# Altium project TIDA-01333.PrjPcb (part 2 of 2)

## Sheet TIDA-01333_Power_Stage.SchDoc: Power Stage
size 431 x 279 mm; Date: Not shown in title block; ApprovedBy: Not shown in title block; CheckedBy: Not shown in title block; Author: Not shown in title block; CompanyName: Not shown in title block; DrawnBy: Tobias Puetz; Engineer: Not shown in title block; Organization: Not shown in title block; Address1: Not shown in title block; Address2: Not shown in title block; Address3: Not shown in title block; Address4: Not shown in title block; DocumentNumber: 4; Revision: Use project parameter SCH_Rev; SheetNumber: 4; SheetTotal: 10; PageSetup: Record=PageOptions¦CenterHorizontal=True¦CenterVertical=True¦PrintScale=0.66¦XCorrection=1.00¦YCorrection=1.00¦PrintKind=0¦BorderSize=5000000¦LeftOffset=0¦BottomOffset=0¦Orientation=2¦PaperLength=1000¦PaperWidth=1000¦Scale=100¦PaperSource=15¦PrintQuality=600¦MediaType=1¦DitherType=10¦PrintScaleMode=1¦PaperKind=Letter
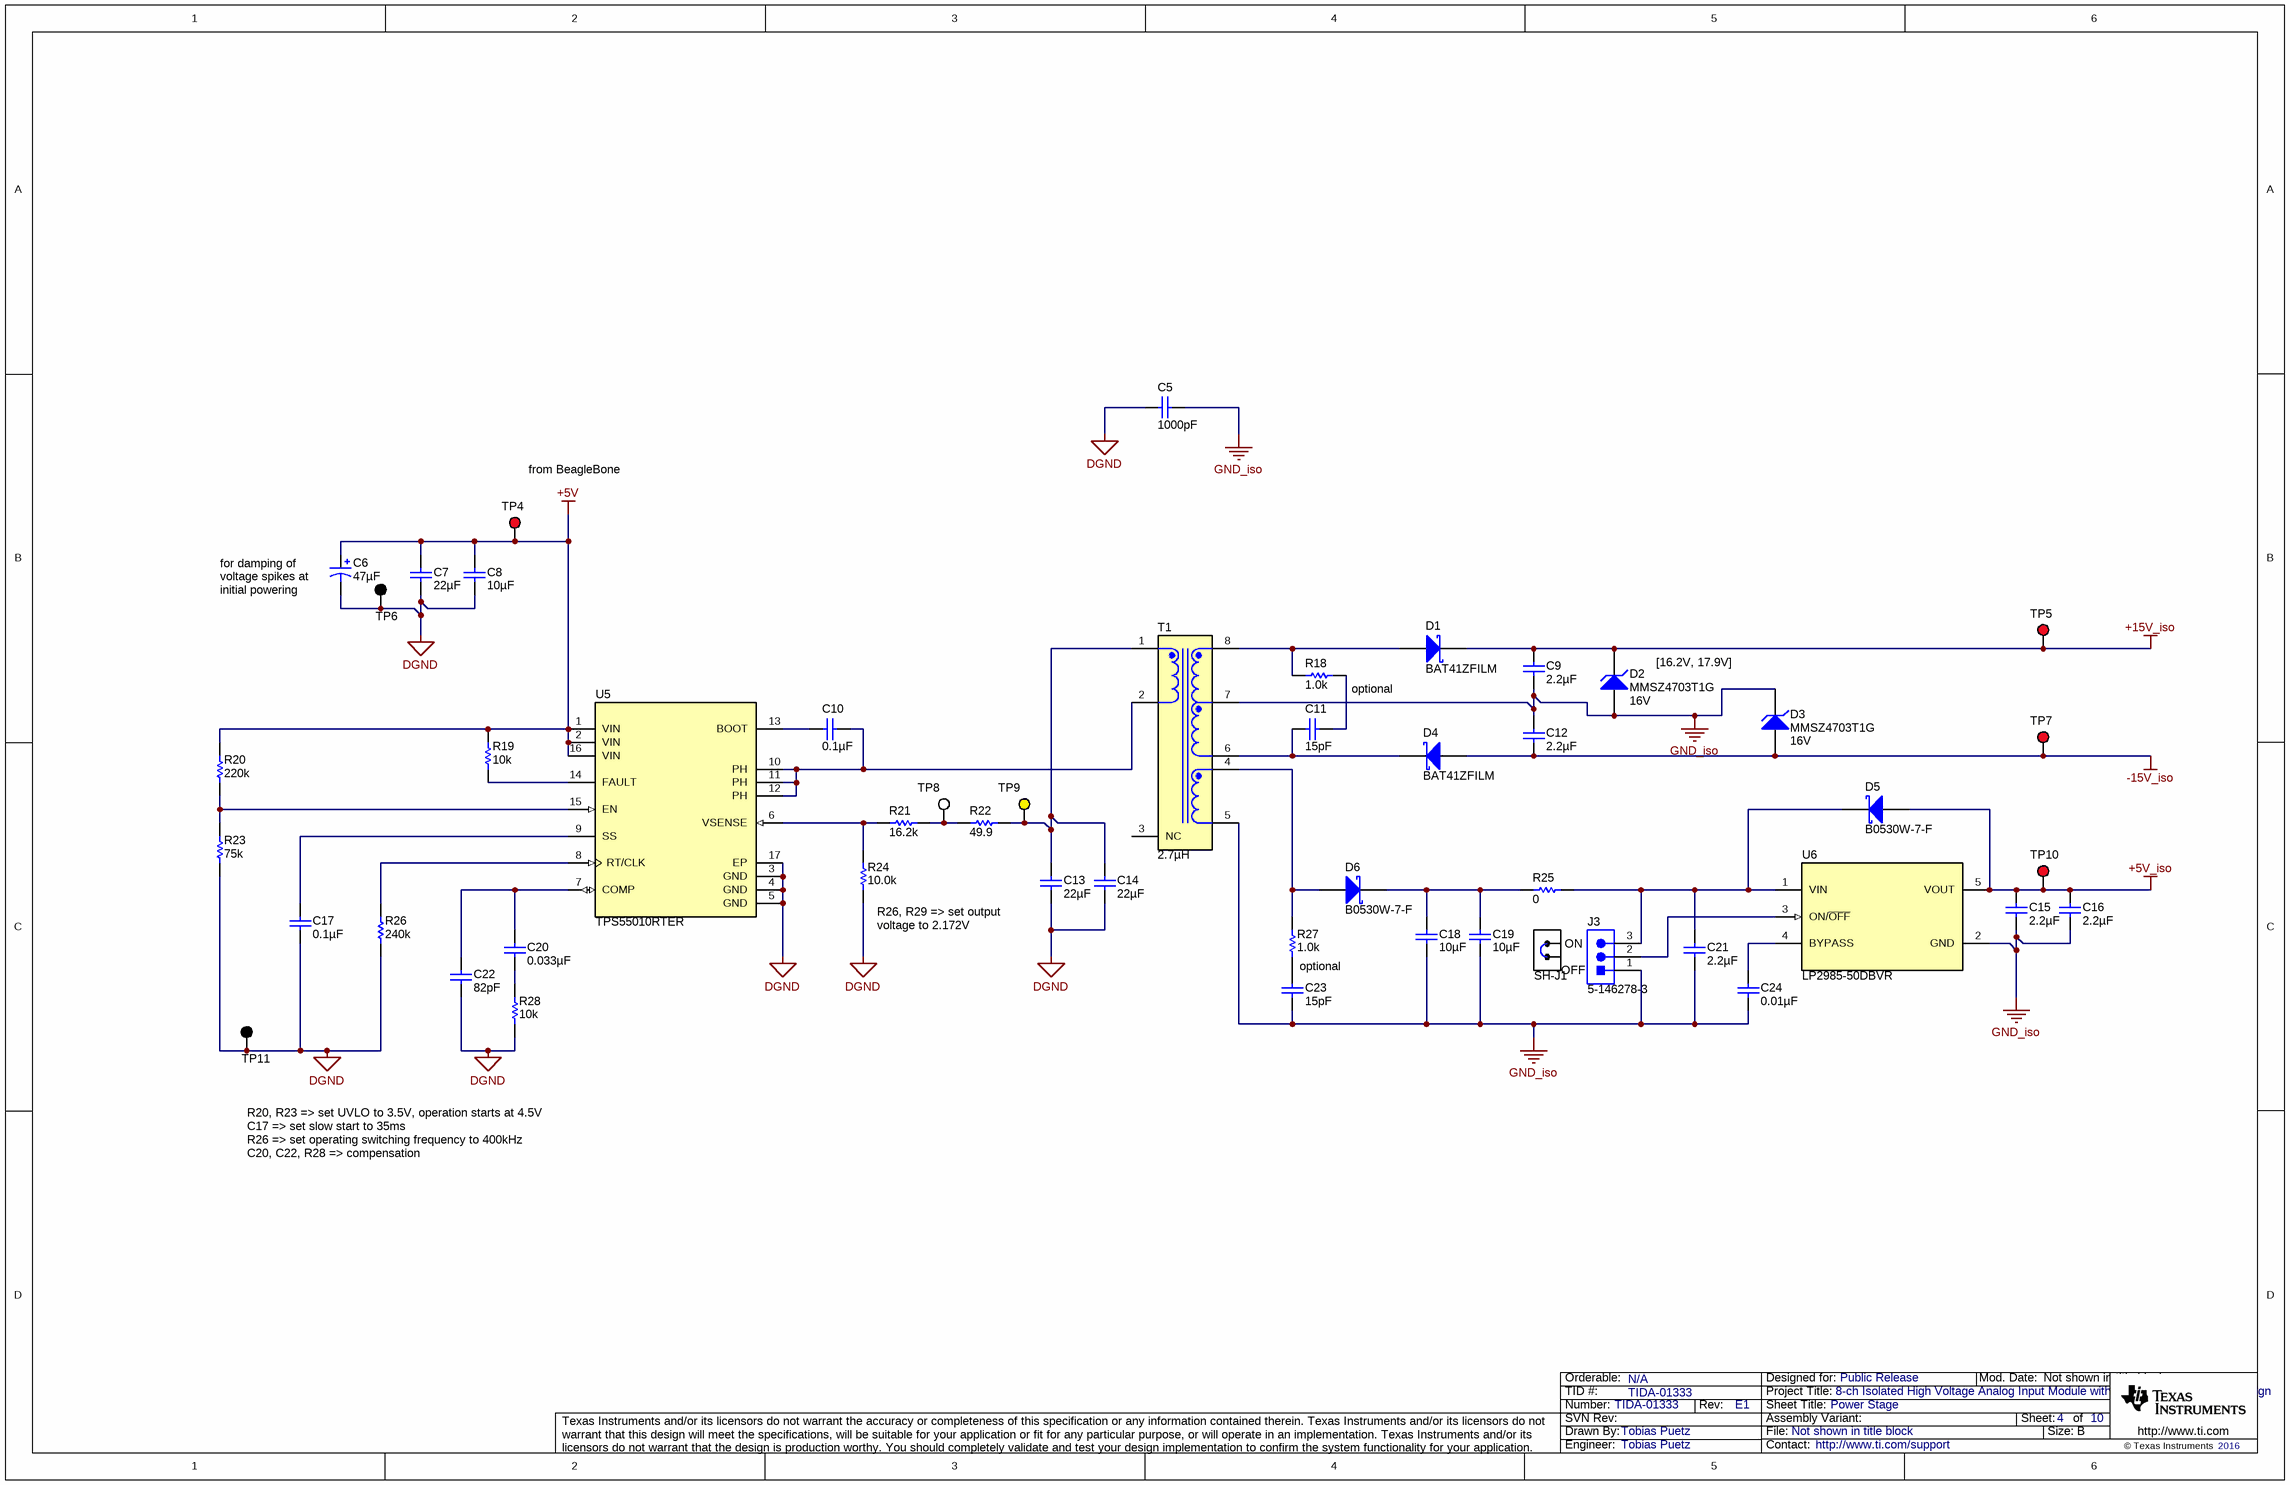
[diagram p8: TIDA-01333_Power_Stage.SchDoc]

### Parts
C5  ValueDisplayed: 1000pF  [1206_190]  (hidden comment: 202R18W102KV4E)
C6  ValueDisplayed: 47µF  [CAPPRD200W50D500H1100]  (hidden comment: ECA-1VM470)
C7  ValueDisplayed: 22µF  [1206_180]  (hidden comment: GRM31CR71A226KE15L)
C8  ValueDisplayed: 10µF  [0805_HV]  (hidden comment: C2012X7R1A106K125AC)
C9  ValueDisplayed: 2.2µF  [1206_180]  (hidden comment: GRM31CR71H225KA88L)
C10  ValueDisplayed: 0.1µF  [0603]  (hidden comment: GRM188R71H104KA93D)
C11  ValueDisplayed: 15pF  [0603]  (hidden comment: GRM1885C1H150JA01D)
C12  ValueDisplayed: 2.2µF  [1206_180]  (hidden comment: GRM31CR71H225KA88L)
C13  ValueDisplayed: 22µF  [1206_180]  (hidden comment: GRM31CR71A226KE15L)
C14  ValueDisplayed: 22µF  [1206_180]  (hidden comment: GRM31CR71A226KE15L)
C15  ValueDisplayed: 2.2µF  [0603]  (hidden comment: GRM188R71A225KE15D)
C16  ValueDisplayed: 2.2µF  [0603]  (hidden comment: GRM188R71A225KE15D)
C17  ValueDisplayed: 0.1µF  [0603]  (hidden comment: GRM188R71H104KA93D)
C18  ValueDisplayed: 10µF  [0805_HV]  (hidden comment: C2012X7R1A106K125AC)
C19  ValueDisplayed: 10µF  [0805_HV]  (hidden comment: C2012X7R1A106K125AC)
C20  ValueDisplayed: 0.033µF  [0603]  (hidden comment: GRM188R71H333KA61D)
C21  ValueDisplayed: 2.2µF  [0603]  (hidden comment: GRM188R71A225KE15D)
C22  ValueDisplayed: 82pF  [0603]  (hidden comment: GRM1885C1H820JA01D)
C23  ValueDisplayed: 15pF  [0603]  (hidden comment: GRM1885C1H150JA01D)
C24  ValueDisplayed: 0.01µF  [0603]  (hidden comment: 06031C103KAT2A)
D1  BAT41ZFILM  [SOD-123]
D2  MMSZ4703T1G  value 16V  [SOD-123]
D3  MMSZ4703T1G  value 16V  [SOD-123]
D4  BAT41ZFILM  [SOD-123]
D5  B0530W-7-F  [SOD-123]
D6  B0530W-7-F  [SOD-123]
J3  5-146278-3  [TE_5-146278-3]
R18  ValueDisplayed: 1.0k  [0805_HV]  (hidden comment: ERJ-6GEYJ102V)
R19  ValueDisplayed: 10k  [0603]  (hidden comment: CRCW060310K0JNEA)
R20  ValueDisplayed: 220k  [0603]  (hidden comment: CRCW0603220KJNEA)
R21  ValueDisplayed: 16.2k  [0603]  (hidden comment: CRCW060316K2FKEA)
R22  ValueDisplayed: 49.9  [0603]  (hidden comment: CRCW060349R9FKEA)
R23  ValueDisplayed: 75k  [0603]  (hidden comment: CRCW060375K0JNEA)
R24  ValueDisplayed: 10.0k  [0603]  (hidden comment: CRCW060310K0FKEA)
R25  ValueDisplayed: 0  [0603]  (hidden comment: CRCW06030000Z0EA)
R26  ValueDisplayed: 240k  [0603]  (hidden comment: CRCW0603240KJNEA)
R27  ValueDisplayed: 1.0k  [0805_HV]  (hidden comment: ERJ-6GEYJ102V)
R28  ValueDisplayed: 10k  [0603]  (hidden comment: CRCW060310K0JNEA)
SH-J1  60900213421  [Wurth_60900213421]  (value not drawn)
T1  ValueDisplayed: 2.7µH  [Wurth_750316170]  (hidden comment: 750316449)
TP4  5000  [Keystone5000]  (value not drawn)
TP5  5000  [Keystone5000]  (value not drawn)
TP6  5001  [Keystone5001]  (value not drawn)
TP7  5000  [Keystone5000]  (value not drawn)
TP8  5002  [Keystone5002]  (value not drawn)
TP9  5004  [Keystone5004]  (value not drawn)
TP10  5000  [Keystone5000]  (value not drawn)
TP11  5001  [Keystone5001]  (value not drawn)
U5  TPS55010RTER  [RTE0016F]
U6  LP2985-50DBVR  [DBV0005A_N]

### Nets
+5V: C6.1(+) C7.1 C8.2 R19.2 R20.2 TP4.1 U5.1(VIN) U5.2(VIN) U5.16(VIN)
+5V_iso: C15.1 C16.1 D5.2(A) TP10.1 U6.5(VOUT)
+15V_iso: C9.1 D1.1(K) D2.1(K) TP5.1
-15V_iso: C12.2 D3.2(A) D4.2(A) TP7.1
DGND: C5.2 C6.2(-) C7.2 C8.1 C13.2 C14.2 C17.2 C22.1 R23.1 R24.1 R26.1 R28.1 TP6.1 TP11.1 U5.3(GND) U5.4(GND) U5.5(GND) U5.17(EP)
GND_iso: C5.1 C9.2 C12.1 C15.2 C16.2 C18.2 C19.1 C21.2 C23.2 C24.2 D2.2(A) D3.1(K) J3.1 T1.5 T1.7 U6.2(GND)
NetC10_1: C10.1 T1.2 U5.10(PH) U5.11(PH) U5.12(PH)
NetC10_2: C10.2 U5.13(BOOT)
NetC11_1: C11.1 R18.1
NetC11_2: C11.2 D4.1(K) T1.6
NetC13_1: C13.1 C14.1 R22.2 T1.1 TP9.1
NetC17_1: C17.1 U5.9(SS)
NetC18_1: C18.1 C19.2 D6.1(K) R25.1
NetC20_1: C20.1 C22.2 U5.7(COMP)
NetC20_2: C20.2 R28.2
NetC21_1: C21.1 D5.1(K) J3.3 R25.2 U6.1(VIN)
NetC23_1: C23.1 R27.1
NetC24_1: C24.1 U6.4(BYPASS)
NetD1_2: D1.2(A) R18.2 T1.8
NetD6_2: D6.2(A) R27.2 T1.4
NetJ3_2: J3.2 U6.3(ON/~{OFF})
NetR19_1: R19.1 U5.14(FAULT)
NetR20_1: R20.1 R23.2 U5.15(EN)
NetR21_1: R21.1 R22.1 TP8.1
NetR21_2: R21.2 R24.2 U5.6(VSENSE)
NetR26_2: R26.2 U5.8(RT/CLK)

Not connected (* = marked no-connect by the designer): T1 3(NC)

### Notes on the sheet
- from BeagleBone
- (near C6) for damping of voltage spikes at initial powering
- (near R18) optional
- [16.2V, 17.9V]
- (near R24) R26, R29 => set output voltage to 2.172V
- (near R27) optional
- ON
- OFF
- R20, R23 => set UVLO to 3.5V, operation starts at 4.5V
  C17 => set slow start to 35ms
  R26 => set operating switching frequency to 400kHz
  C20, C22, R28 => compensation

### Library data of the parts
C5 = 202R18W102KV4E: CAP, CERM, 1000 pF, 2000 V, +/- 10%, X7R, 1206_190; Manufacturer: Johanson Technology; Polarized: N; CompType: Capacitor; Value: 1000pF; U/M: EA; Cap_F: 0.000000001; Tolerance_%: 10; Value1: Unknown; VDC_V: 2000; Value2: 2000V; TaMin_C: -55; TaMax_C: 125; Cap_Case: 1206; AEC Category: Q200; SizeArea_mm2: 5.12; SizeAreaWB_mm2: 10.92; SizeX_mm: 3.2; SizeY_mm: 1.6; SizeZ_mm: 1.9
C6 = ECA-1VM470: CAP, AL, 47 µF, 35 V, +/- 20%, TH; Manufacturer: Panasonic; Polarized: Y; CompType: Capacitor; Value: 47uF; U/M: EA; Cap_F: 0.000047; Tolerance_%: 20; Value1: Unknown; VDC_V: 35; Value2: 35V; IRMS_A: 0.13; TaMin_C: -40; TaMax_C: 85; Cap_Case: RCAP, 5x11mm; AEC Category: Q200; AEC Qualified: N
C7 C13 C14 = GRM31CR71A226KE15L: CAP, CERM, 22 µF, 10 V, +/- 10%, X7R, 1206; Manufacturer: MuRata; Polarized: N; CompType: Capacitor; Value: 22uF; U/M: EA; Cap_F: 0.000022; Tolerance_%: 10; Value1: Unknown; Value2: 10V; TaMin_C: -55; TaMax_C: 125; Cap_Case: 1206; AEC Category: Q200; SizeArea_mm2: 5.12; SizeAreaWB_mm2: 10.92; SizeX_mm: 3.2; SizeY_mm: 1.6; SizeZ_mm: 1.8
C8 C18 C19 = C2012X7R1A106K125AC: CAP, CERM, 10 µF, 10 V, +/- 10%, X7R, 0805; Manufacturer: TDK; Polarized: N; CompType: Capacitor; Value: 10uF; U/M: EA; Cap_F: 0.00001; Tolerance_%: 10; ESR_ohm: 0.001063; Value1: 0.001063 ohm; Value2: 10V; IRMS_A: 6.32908; TaMin_C: -55; TaMax_C: 125; Cap_Case: 0805; AEC Category: Q200; SizeArea_mm2: 2.5; SizeAreaWB_mm2: 6.75; SizeX_mm: 2; SizeY_mm: 1.25; SizeZ_mm: 1.45
C9 C12 = GRM31CR71H225KA88L: CAP, CERM, 2.2 µF, 50 V, +/- 10%, X7R, 1206; Manufacturer: MuRata; Polarized: N; CompType: Capacitor; Value: 2.2uF; U/M: EA; Cap_F: 0.0000022; Tolerance_%: 10; Value1: Unknown; VDC_V: 50; Value2: 50V; TaMin_C: -55; TaMax_C: 125; Cap_Case: 1206; AEC Category: Q200; SizeArea_mm2: 5.12; SizeAreaWB_mm2: 10.92; SizeX_mm: 3.2; SizeY_mm: 1.6; SizeZ_mm: 1.8
C10 C17 = GRM188R71H104KA93D: CAP, CERM, 0.1 µF, 50 V, +/- 10%, X7R, 0603; Manufacturer: MuRata; Polarized: N; CompType: Capacitor; Value: 0.1uF; U/M: EA; Cap_F: 0.0000001; Tolerance_%: 10; Value1: Unknown; VDC_V: 50; Value2: 50V; TaMin_C: -55; TaMax_C: 125; SizeArea_mm2: 1.28; SizeAreaWB_mm2: 4.68; SizeX_mm: 1.6; SizeY_mm: 0.8; SizeZ_mm: 1; AEC Category: Q200
C11 C23 = GRM1885C1H150JA01D: CAP, CERM, 15 pF, 50 V, +/- 5%, C0G/NP0, 0603; Manufacturer: MuRata; Polarized: N; CompType: Capacitor; Value: 15pF; U/M: EA; Cap_F: 0.000000000015; Tolerance_%: 5; Value1: Unknown; VDC_V: 50; Value2: 50V; TaMin_C: -55; TaMax_C: 125; SizeArea_mm2: 1.28; SizeAreaWB_mm2: 4.68; SizeX_mm: 1.6; SizeY_mm: 0.8; SizeZ_mm: 1; AEC Category: Q200
C15 C16 C21 = GRM188R71A225KE15D: CAP, CERM, 2.2 µF, 10 V, +/- 10%, X7R, 0603; Manufacturer: MuRata; Polarized: N; CompType: Capacitor; Value: 2.2uF; U/M: EA; Cap_F: 0.0000022; Tolerance_%: 10; ESR_ohm: 0.009; Value1: 0.009 ohm; Value2: 10V; TaMin_C: -55; TaMax_C: 125; AEC Category: Q200; SizeArea_mm2: 1.28; SizeAreaWB_mm2: 4.68; SizeX_mm: 1.6; SizeY_mm: 0.8; SizeZ_mm: 1
C20 = GRM188R71H333KA61D: CAP, CERM, 0.033 µF, 50 V, +/- 10%, X7R, 0603; Manufacturer: MuRata; Polarized: N; CompType: Capacitor; Value: 0.033uF; U/M: EA; Cap_F: 0.000000033; Tolerance_%: 10; Value1: Unknown; VDC_V: 50; Value2: 50V; TaMin_C: -55; TaMax_C: 125; AEC Category: Q200; SizeArea_mm2: 1.28; SizeAreaWB_mm2: 4.68; SizeX_mm: 1.6; SizeY_mm: 0.8; SizeZ_mm: 1
C22 = GRM1885C1H820JA01D: CAP, CERM, 82 pF, 50 V, +/- 5%, C0G/NP0, 0603; Manufacturer: MuRata; Polarized: N; CompType: Capacitor; Value: 82pF; U/M: EA; Cap_F: 0.000000000082; Tolerance_%: 5; Value1: Unknown; VDC_V: 50; Value2: 50V; TaMin_C: -55; TaMax_C: 125; AEC Category: Q200; SizeArea_mm2: 1.28; SizeAreaWB_mm2: 4.68; SizeX_mm: 1.6; SizeY_mm: 0.8; SizeZ_mm: 1
C24 = 06031C103KAT2A: CAP, CERM, 0.01 µF, 100 V, +/- 10%, X7R, 0603; Manufacturer: AVX; Polarized: N; CompType: Capacitor; Value: 0.01uF; U/M: EA; Cap_F: 0.00000001; Tolerance_%: 10; ESR_ohm: 0.098; Value1: 0.098 ohm; VDC_V: 100; Value2: 100V; TaMin_C: -55; TaMax_C: 125; SizeArea_mm2: 1.28; SizeAreaWB_mm2: 4.68; SizeX_mm: 1.6; SizeY_mm: 0.8; SizeZ_mm: 1; AEC Category: Q200
D1 D4 = BAT41ZFILM: Diode, Schottky, 100 V, 0.2 A, SOD-123; Manufacturer: STMicroelectronics; U/M: EA; Vf_V: 1; Value: 100V; Value1: 0.2A; Value2: 1V; Io_A: 0.2; Vr_V: 100; TJmax_C: 150; SizeAreaWB_mm2: 13.095; SizeArea_mm2: 6.545; SizeX_mm: 3.85; SizeY_mm: 1.7; SizeZ_mm: 1.35; AEC Category: Q101
D2 D3 = MMSZ4703T1G: Diode, Zener, 16 V, 500 mW, SOD-123; Manufacturer: ON Semiconductor; SymbolCreator: a0412235; U/M: EA; Power_W: 0.5; Vz_V: 16; Value1: 0.5W; RJA_CperW: 340; AEC Category: Q101; SizeAreaWB_mm2: 13.095; SizeArea_mm2: 6.545; SizeX_mm: 3.85; SizeY_mm: 1.7; SizeZ_mm: 1.35
D5 D6 = B0530W-7-F: Diode, Schottky, 30 V, 0.5 A, SOD-123; Manufacturer: Diodes Inc.; U/M: EA; Vf_V: 0.43; Value: 30V; Value1: 0.5A; Value2: 0.43V; Io_A: 0.5; Vr_V: 30; TJmax_C: 125; AEC Category: Q101; SizeAreaWB_mm2: 13.095; SizeArea_mm2: 6.545; SizeX_mm: 3.85; SizeY_mm: 1.7; SizeZ_mm: 1.35
J3 = 5-146278-3: Header, 100mil, 3x1, Tin, TH; Manufacturer: TE Connectivity; SymbolCreator: a0799628
R18 R27 = ERJ-6GEYJ102V: RES, 1.0 k, 5%, 0.125 W, 0805; Manufacturer: Panasonic; CompType: Resistor; Value: 1.0k; Res_ohm: 1000; Value_Code: 1k00; Tolerance_%: 5; Power_W: 0.125; Value2: 0.125W; VDC_V: 150; TempCo: 200 ppm/C; EIA_Code: E24; U/M: EA; AEC Category: Q200; SizeArea_mm2: 2.5; SizeX_mm: 2; SizeY_mm: 1.25; SizeZ_mm: 1.45
R19 R28 = CRCW060310K0JNEA: RES, 10 k, 5%, 0.1 W, 0603; Manufacturer: Vishay-Dale; CompType: Resistor; Value: 10k; Res_ohm: 10000; Value_Code: 10k0; Tolerance_%: 5; Power_W: 0.1; Value2: 0.1W; VDC_V: 75; TempCo: 200 ppm/C; EIA_Code: E24; U/M: EA; AEC Category: Q200; SizeArea_mm2: 1.28; SizeX_mm: 1.6; SizeY_mm: 0.8; SizeZ_mm: 1
R20 = CRCW0603220KJNEA: RES, 220 k, 5%, 0.1 W, 0603; Manufacturer: Vishay-Dale; CompType: Resistor; Value: 220k; Res_ohm: 220000; Tolerance_%: 5; Power_W: 0.1; Value2: 0.1W; VDC_V: 75; TempCo: 200 ppm/C; EIA_Code: E24; U/M: EA; AEC Category: Q200; SizeArea_mm2: 1.28; SizeX_mm: 1.6; SizeY_mm: 0.8; SizeZ_mm: 1
R21 = CRCW060316K2FKEA: RES, 16.2 k, 1%, 0.1 W, 0603; Manufacturer: Vishay-Dale; CompType: Resistor; Value: 16.2k; Res_ohm: 16200; Value_Code: 16k2; Tolerance_%: 1; Power_W: 0.1; Value2: 0.1W; VDC_V: 75; TempCo: 100 ppm/C; EIA_Code: E96; U/M: EA; AEC Category: Q200; SizeArea_mm2: 1.28; SizeX_mm: 1.6; SizeY_mm: 0.8
R22 = CRCW060349R9FKEA: RES, 49.9, 1%, 0.1 W, 0603; Manufacturer: Vishay-Dale; CompType: Resistor; Value: 49.9; Value_Code: 49R9; Tolerance_%: 1; Power_W: 0.1; Value2: 0.1W; VDC_V: 75; TempCo: 100 ppm/C; SizeArea_mm2: 1.28; SizeX_mm: 1.6; SizeY_mm: 0.8; EIA_Code: E96; U/M: EA; AEC Category: Q200
R23 = CRCW060375K0JNEA: RES, 75 k, 5%, 0.1 W, 0603; Manufacturer: Vishay-Dale; CompType: Resistor; Value: 75k; Res_ohm: 75000; Value_Code: 75k0; Tolerance_%: 5; Power_W: 0.1; Value2: 0.1W; VDC_V: 75; TempCo: 200 ppm/C; SizeArea_mm2: 1.28; SizeX_mm: 1.6; SizeY_mm: 0.8; SizeZ_mm: 1; EIA_Code: E24; U/M: EA; AEC Category: Q200
R24 = CRCW060310K0FKEA: RES, 10.0 k, 1%, 0.1 W, 0603; Manufacturer: Vishay-Dale; CompType: Resistor; Value: 10.0k; Res_ohm: 10000; Value_Code: 10k0; Tolerance_%: 1; Power_W: 0.1; Value2: 0.1W; VDC_V: 75; TempCo: 100 ppm/C; EIA_Code: E96; U/M: EA; AEC Category: Q200; SizeArea_mm2: 1.28; SizeX_mm: 1.6; SizeY_mm: 0.8
R25 = CRCW06030000Z0EA: RES, 0, 5%, 0.1 W, 0603; Manufacturer: Vishay-Dale; CompType: Resistor; Value: 0; Value_Code: 0000; Tolerance_%: 5; Power_W: 0.1; Value2: 0.1W; VDC_V: 75; TempCo: 200 ppm/C; EIA_Code: E24; U/M: EA; AEC Category: Q200; SizeArea_mm2: 1.28; SizeX_mm: 1.6; SizeY_mm: 0.8; SizeZ_mm: 1
R26 = CRCW0603240KJNEA: RES, 240 k, 5%, 0.1 W, 0603; Manufacturer: Vishay-Dale; CompType: Resistor; Value: 240k; Res_ohm: 240000; Tolerance_%: 5; Power_W: 0.1; Value2: 0.1W; VDC_V: 75; TempCo: 200 ppm/C; EIA_Code: E24; U/M: EA; AEC Category: Q200; SizeArea_mm2: 1.28; SizeX_mm: 1.6; SizeY_mm: 0.8; SizeZ_mm: 1
SH-J1 = 60900213421: Shunt, 2.54mm, Gold, Black; Manufacturer: Wurth Elektronik
T1 = 750316449: Transformer, 2.7 uH, SMT; Manufacturer: Wurth Elektronik; SymbolCreator: Altium; Value: 2.7uH; Lp: 2.7; DCR_ohm: 0.015; LeakageL: 0.5; Ns1toNp: 7; Ns3toNp: 3; Rs1: 1.45; Rs3: 0.435
TP4 TP5 TP7 TP10 = 5000: Test Point, Miniature, Red, TH; Manufacturer: Keystone; CompType: Test Point Loop; ContactFinish: Silver
TP6 TP11 = 5001: Test Point, Miniature, Black, TH; Manufacturer: Keystone; CompType: Test Point Loop; ContactFinish: Silver
TP8 = 5002: Test Point, Miniature, White, TH; Manufacturer: Keystone; CompType: Test Point Loop; ContactFinish: Silver
TP9 = 5004: Test Point, Miniature, Yellow, TH; Manufacturer: Keystone; CompType: Test Point Loop; ContactFinish: Silver
U5 = TPS55010RTER: 2.95V To 6V Input, 2W, Isolated DC/DC Converter with Integrated FETs, RTE0016F (WQFN-16); Manufacturer: Texas Instruments; SymbolCreator: Altium; SizeArea_mm2: 9; SizeAreaWB_mm2: 16; SizeX_mm: 3; SizeZ_mm: 0.8; CompType: IC; U/M: EA
U6 = LP2985-50DBVR: 150-mA Low-noise Low-dropout Regulator With Shutdown, DBV0005A; Alternate PartNumber: LP2985-50DBVT; Manufacturer: Texas Instruments; SymbolCreator: Altium; CompType: IC; U/M: EA; SizeArea_mm2: 8.12; SizeAreaWB_mm2: 14.82; SizeX_mm: 2.8; SizeY_mm: 2.9; SizeZ_mm: 1.45

## Sheet TIDA-01333_CoverSheet.SchDoc: Block Diagram
size 431 x 279 mm; Date: Not shown in title block; ApprovedBy: Not shown in title block; CheckedBy: Not shown in title block; Author: Not shown in title block; CompanyName: Not shown in title block; DrawnBy: Tobias Puetz; Engineer: Not shown in title block; Organization: Not shown in title block; Address1: Not shown in title block; Address2: Not shown in title block; Address3: Not shown in title block; Address4: Not shown in title block; DocumentNumber: 1; Revision: Use project parameter SCH_Rev; SheetNumber: 1; SheetTotal: 10; PageSetup: Record=PageOptions¦CenterHorizontal=True¦CenterVertical=True¦PrintScale=1.00¦XCorrection=1.00¦YCorrection=1.00¦PrintKind=0¦BorderSize=5000000¦LeftOffset=0¦BottomOffset=0¦Orientation=2¦PaperLength=1000¦PaperWidth=1000¦Scale=100¦PaperSource=15¦PrintQuality=600¦MediaType=1¦DitherType=10¦PaperKind=Letter¦PrintScaleMode=1
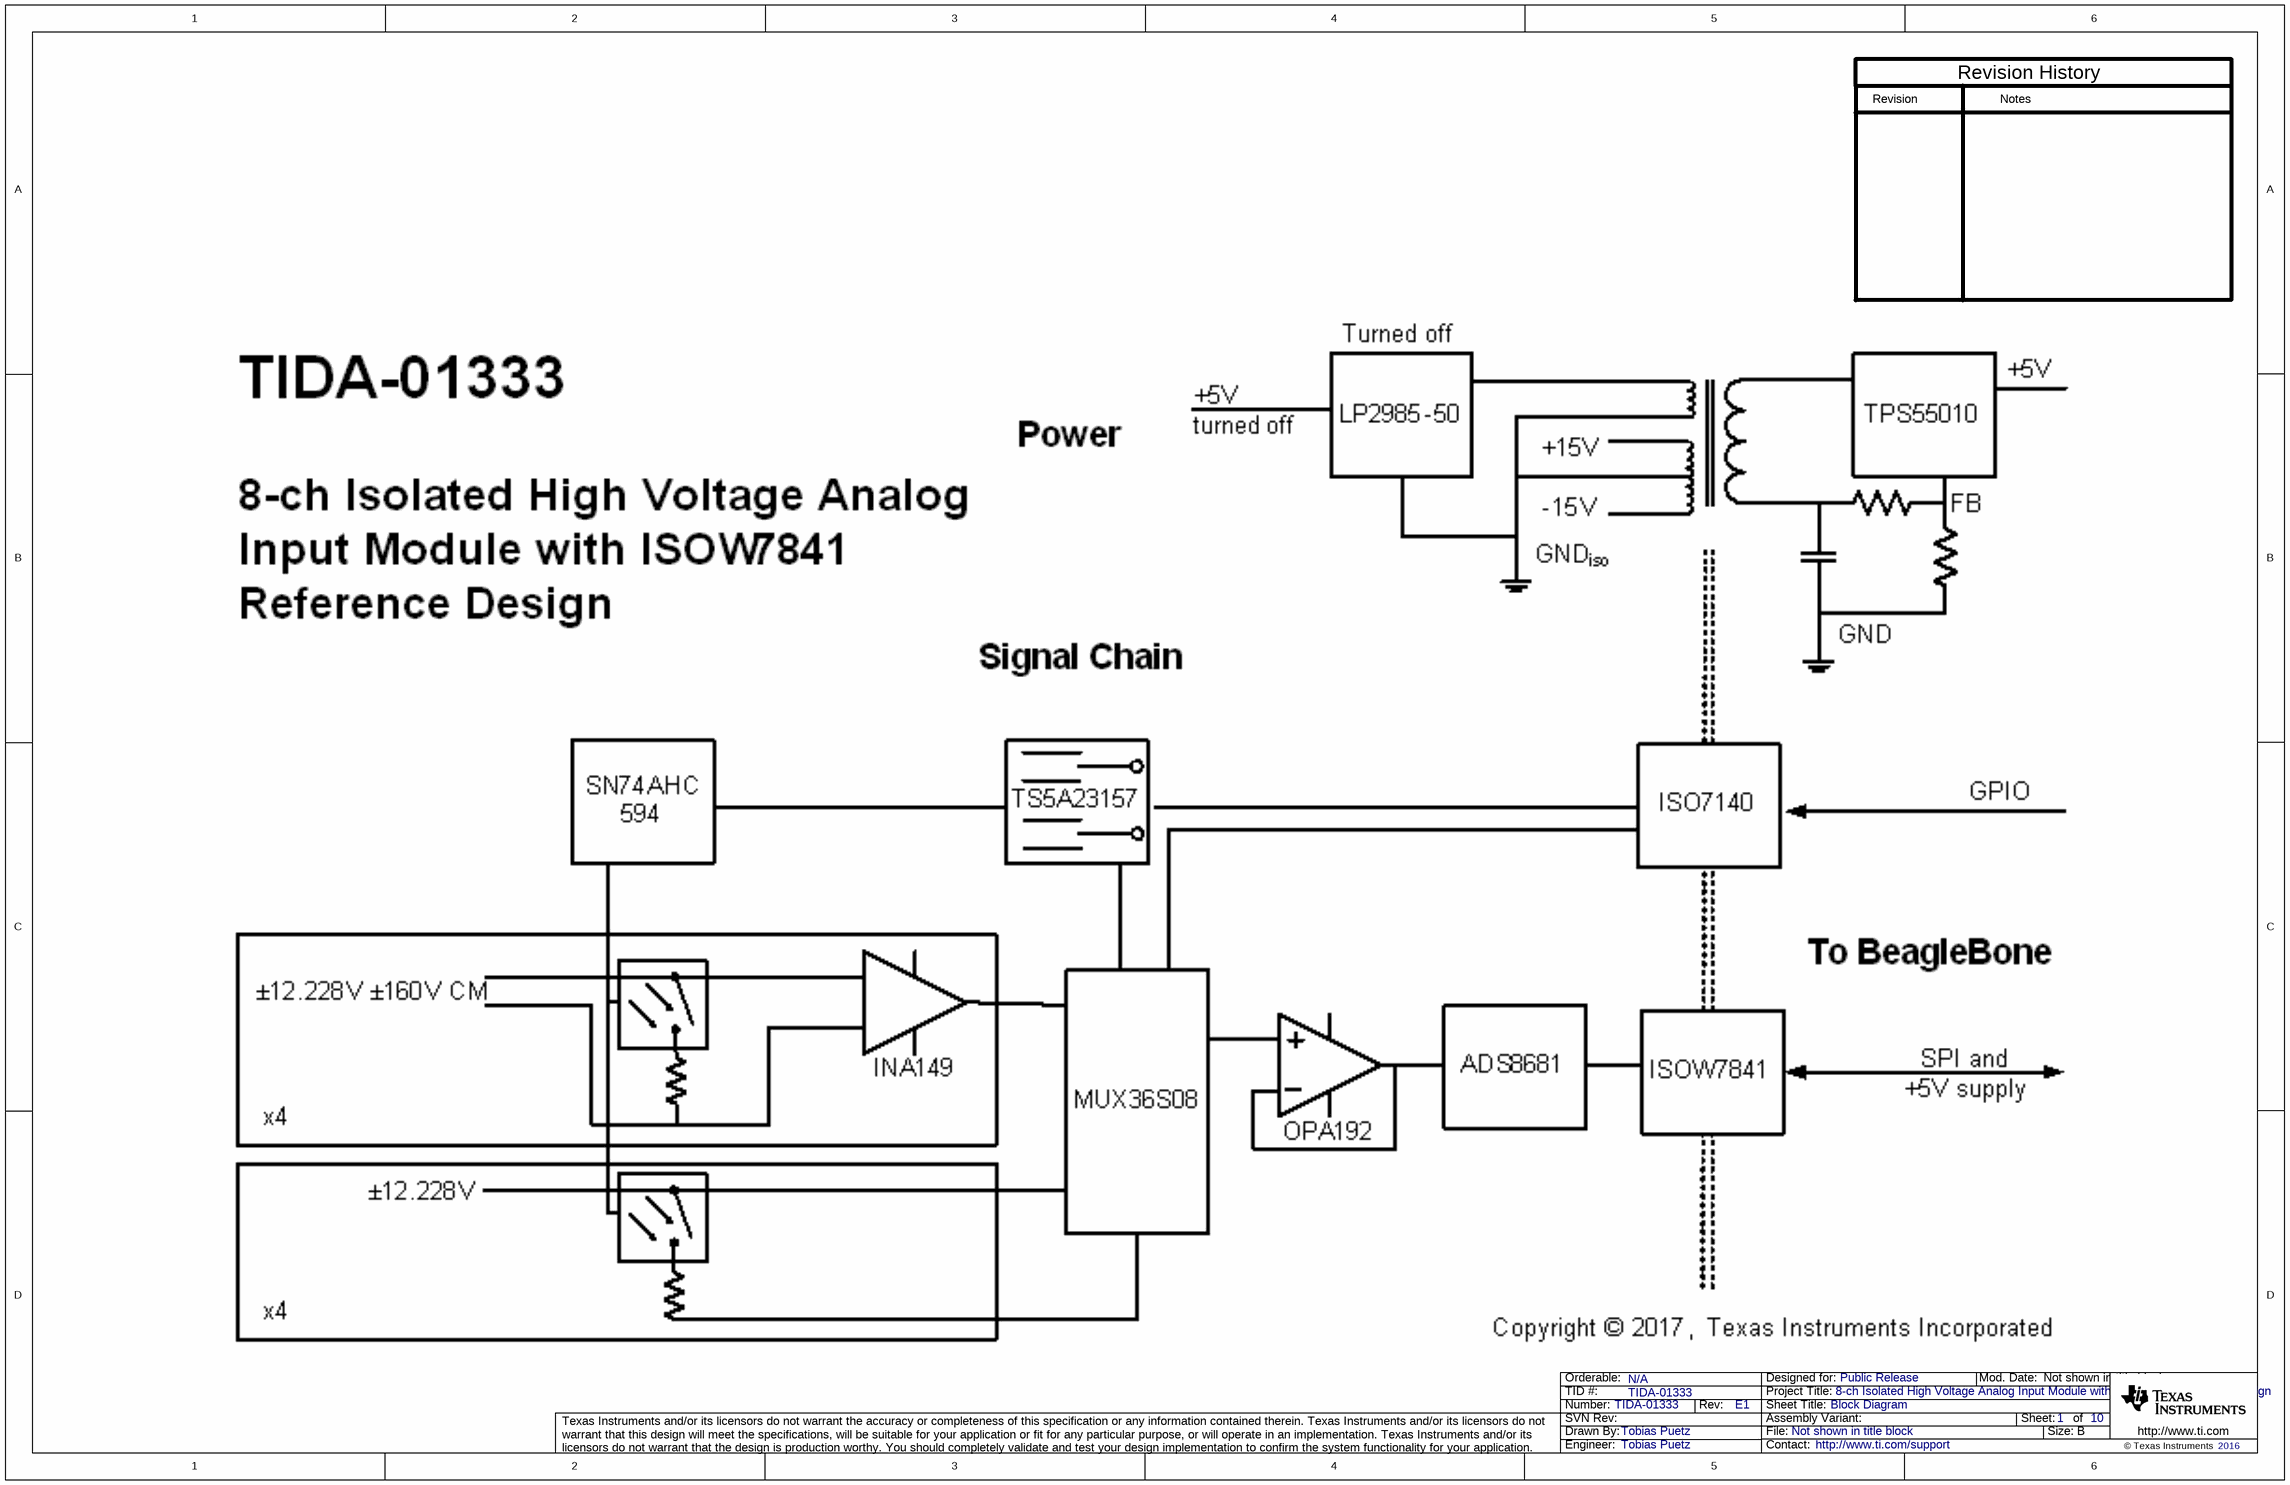
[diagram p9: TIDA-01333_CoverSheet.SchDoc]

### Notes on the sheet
- Revision
- Notes
- Revision History

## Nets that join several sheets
+5V: TIDA-01333_Cape (NT1.2), TIDA-01333_Digital_Isolation (6 pins), TIDA-01333_Power_Stage (9 pins)
+5V_iso: TIDA-01333_MUX_Stage (9 pins), TIDA-01333_Digital_Isolation (7 pins), TIDA-01333_Power_Stage (5 pins)
+15V_iso: U_TIDA-00764_Signal_Chain/Channel_Inputs/CMCh1 (C30_CMCh1.1 C31_CMCh1.1 U7_CMCh1.7), U_TIDA-00764_Signal_Chain/Channel_Inputs/CMCh3 (C30_CMCh3.1 C31_CMCh3.1 U7_CMCh3.7), U_TIDA-00764_Signal_Chain/Channel_Inputs/CMCh2 (C30_CMCh2.1 C31_CMCh2.1 U7_CMCh2.7), U_TIDA-00764_Signal_Chain/Channel_Inputs/CMCh4 (C30_CMCh4.1 C31_CMCh4.1 U7_CMCh4.7), TIDA-01333_MUX_Stage (C46.1 C47.1 U11.13 U13.5), TIDA-01333_Power_Stage (C9.1 D1.1 D2.1 TP5.1)
-15V_iso: U_TIDA-00764_Signal_Chain/Channel_Inputs/CMCh1 (C25_CMCh1.2 C26_CMCh1.2 U7_CMCh1.4), U_TIDA-00764_Signal_Chain/Channel_Inputs/CMCh3 (C25_CMCh3.2 C26_CMCh3.2 U7_CMCh3.4), U_TIDA-00764_Signal_Chain/Channel_Inputs/CMCh2 (C25_CMCh2.2 C26_CMCh2.2 U7_CMCh2.4), U_TIDA-00764_Signal_Chain/Channel_Inputs/CMCh4 (C25_CMCh4.2 C26_CMCh4.2 U7_CMCh4.4), TIDA-01333_MUX_Stage (C40.2 C43.2 U11.3 U13.2), TIDA-01333_Power_Stage (C12.2 D3.2 D4.2 TP7.1)
DGND: TIDA-01333_Cape (21 pins), TIDA-01333_Digital_Isolation (9 pins), TIDA-01333_Power_Stage (18 pins)
DVDD: TIDA-01333_Cape (20 pins), TIDA-01333_Digital_Isolation (C37.1 U9.5)
GND_iso: TIDA-01333_Signal_Chain (5 pins), U_TIDA-00764_Signal_Chain/Channel_Inputs/CMCh1 (11 pins), U_TIDA-00764_Signal_Chain/Channel_Inputs/CMCh3 (11 pins), U_TIDA-00764_Signal_Chain/Channel_Inputs/CMCh2 (11 pins), U_TIDA-00764_Signal_Chain/Channel_Inputs/CMCh4 (11 pins), U_TIDA-00764_Signal_Chain/Channel_Inputs/NoCMCh1 (C32_NoCMCh1.2 D11_NoCMCh1.2 D12_NoCMCh1.1 R32_NoCMCh1.1), U_TIDA-00764_Signal_Chain/Channel_Inputs/NoCMCh2 (C32_NoCMCh2.2 D11_NoCMCh2.2 D12_NoCMCh2.1 R32_NoCMCh2.1), U_TIDA-00764_Signal_Chain/Channel_Inputs/NoCMCh3 (C32_NoCMCh3.2 D11_NoCMCh3.2 D12_NoCMCh3.1 R32_NoCMCh3.1), U_TIDA-00764_Signal_Chain/Channel_Inputs/NoCMCh4 (C32_NoCMCh4.2 D11_NoCMCh4.2 D12_NoCMCh4.1 R32_NoCMCh4.1), TIDA-01333_MUX_Stage (21 pins), TIDA-01333_Digital_Isolation (7 pins), TIDA-01333_Power_Stage (16 pins)
A0 / SER: TIDA-01333_Cape (R7.2 R8.2), TIDA-01333_Digital_Isolation (TP20.1 U10.5)
A0 / SER_iso: TIDA-01333_MUX_Stage (U15.6), TIDA-01333_Digital_Isolation (U10.12)
A1 / ~{RCLR}: TIDA-01333_Cape (R9.2 R10.2), TIDA-01333_Digital_Isolation (TP21.1 U10.4)
A1 / ~{RCLR}_iso: TIDA-01333_MUX_Stage (U15.10), TIDA-01333_Digital_Isolation (U10.13)
A2: TIDA-01333_Cape (R11.2 R12.2), TIDA-01333_Digital_Isolation (TP22.1 U10.3)
A2_iso: TIDA-01333_MUX_Stage (U11.15), TIDA-01333_Digital_Isolation (U10.14)
Ch_In+: TIDA-01333_Signal_Chain (J4.10), U_TIDA-00764_Signal_Chain/Channel_Inputs/NoCMCh4 (C32_NoCMCh4.1 D12_NoCMCh4.2 K2_NoCMCh4.3), TIDA-01333_MUX_Stage (R42.2)
Ch_In+: TIDA-01333_Signal_Chain (J4.11), U_TIDA-00764_Signal_Chain/Channel_Inputs/NoCMCh3 (C32_NoCMCh3.1 D12_NoCMCh3.2 K2_NoCMCh3.3), TIDA-01333_MUX_Stage (R43.2)
Ch_In+: TIDA-01333_Signal_Chain (J4.12), U_TIDA-00764_Signal_Chain/Channel_Inputs/NoCMCh2 (C32_NoCMCh2.1 D12_NoCMCh2.2 K2_NoCMCh2.3), TIDA-01333_MUX_Stage (R44.2)
Ch_In+: TIDA-01333_Signal_Chain (J4.13), U_TIDA-00764_Signal_Chain/Channel_Inputs/NoCMCh1 (C32_NoCMCh1.1 D12_NoCMCh1.2 K2_NoCMCh1.3), TIDA-01333_MUX_Stage (R45.2)
Ch_V/C_Switch: U_TIDA-00764_Signal_Chain/Channel_Inputs/NoCMCh1 (R31_NoCMCh1.2), TIDA-01333_MUX_Stage (U14.4)
Ch_V/C_Switch: U_TIDA-00764_Signal_Chain/Channel_Inputs/NoCMCh2 (R31_NoCMCh2.2), TIDA-01333_MUX_Stage (U14.5)
Ch_V/C_Switch: U_TIDA-00764_Signal_Chain/Channel_Inputs/NoCMCh3 (R31_NoCMCh3.2), TIDA-01333_MUX_Stage (U14.6)
Ch_V/C_Switch: U_TIDA-00764_Signal_Chain/Channel_Inputs/NoCMCh4 (R31_NoCMCh4.2), TIDA-01333_MUX_Stage (U14.7)
CMCh_In+: TIDA-01333_Signal_Chain (J4.5), U_TIDA-00764_Signal_Chain/Channel_Inputs/CMCh3 (6 pins)
CMCh_In+: TIDA-01333_Signal_Chain (J4.3), U_TIDA-00764_Signal_Chain/Channel_Inputs/CMCh4 (6 pins)
CMCh_In+: TIDA-01333_Signal_Chain (J4.7), U_TIDA-00764_Signal_Chain/Channel_Inputs/CMCh2 (6 pins)
CMCh_In+: TIDA-01333_Signal_Chain (J4.9), U_TIDA-00764_Signal_Chain/Channel_Inputs/CMCh1 (6 pins)
CMCh_In-: TIDA-01333_Signal_Chain (J4.4), U_TIDA-00764_Signal_Chain/Channel_Inputs/CMCh3 (6 pins)
CMCh_In-: TIDA-01333_Signal_Chain (J4.2), U_TIDA-00764_Signal_Chain/Channel_Inputs/CMCh4 (6 pins)
CMCh_In-: TIDA-01333_Signal_Chain (J4.6), U_TIDA-00764_Signal_Chain/Channel_Inputs/CMCh2 (6 pins)
CMCh_In-: TIDA-01333_Signal_Chain (J4.8), U_TIDA-00764_Signal_Chain/Channel_Inputs/CMCh1 (6 pins)
CMCh_Out: U_TIDA-00764_Signal_Chain/Channel_Inputs/CMCh1 (U7_CMCh1.6), TIDA-01333_MUX_Stage (R41.2)
CMCh_Out: U_TIDA-00764_Signal_Chain/Channel_Inputs/CMCh3 (U7_CMCh3.6), TIDA-01333_MUX_Stage (R39.2)
CMCh_Out: U_TIDA-00764_Signal_Chain/Channel_Inputs/CMCh2 (U7_CMCh2.6), TIDA-01333_MUX_Stage (R40.2)
CMCh_Out: U_TIDA-00764_Signal_Chain/Channel_Inputs/CMCh4 (U7_CMCh4.6), TIDA-01333_MUX_Stage (R37.2)
CMCh_V/C_Switch: U_TIDA-00764_Signal_Chain/Channel_Inputs/CMCh1 (R29_CMCh1.2), TIDA-01333_MUX_Stage (U14.15)
CMCh_V/C_Switch: U_TIDA-00764_Signal_Chain/Channel_Inputs/CMCh3 (R29_CMCh3.2), TIDA-01333_MUX_Stage (U14.2)
CMCh_V/C_Switch: U_TIDA-00764_Signal_Chain/Channel_Inputs/CMCh2 (R29_CMCh2.2), TIDA-01333_MUX_Stage (U14.1)
CMCh_V/C_Switch: U_TIDA-00764_Signal_Chain/Channel_Inputs/CMCh4 (R29_CMCh4.2), TIDA-01333_MUX_Stage (U14.3)
CONVST/~{CS}_iso: TIDA-01333_MUX_Stage (U12.11), TIDA-01333_Digital_Isolation (R34.2)
IN1+IN2: TIDA-01333_Cape (R5.2 R6.2), TIDA-01333_Digital_Isolation (TP19.1 U10.6)
IN1+IN2_iso: TIDA-01333_MUX_Stage (U12.9 U15.1 U15.5), TIDA-01333_Digital_Isolation (U10.11)
SCLK_iso: TIDA-01333_MUX_Stage (U12.12), TIDA-01333_Digital_Isolation (R35.2)
SDI_iso: TIDA-01333_MUX_Stage (U12.10), TIDA-01333_Digital_Isolation (R33.2)
SDO1_iso: TIDA-01333_MUX_Stage (R49.1), TIDA-01333_Digital_Isolation (U8.11)
SPI_CLK: TIDA-01333_Cape (J1.31), TIDA-01333_Digital_Isolation (TP16.1 U8.5)
SPI_CSa: TIDA-01333_Cape (U2.4), TIDA-01333_Digital_Isolation (TP17.1 U8.4 U9.1)
SPI_MISO: TIDA-01333_Cape (J1.29), TIDA-01333_Digital_Isolation (R36.1 TP15.1)
SPI_MOSI: TIDA-01333_Cape (J1.30), TIDA-01333_Digital_Isolation (TP18.1 U8.3)

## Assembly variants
001: all parts fitted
